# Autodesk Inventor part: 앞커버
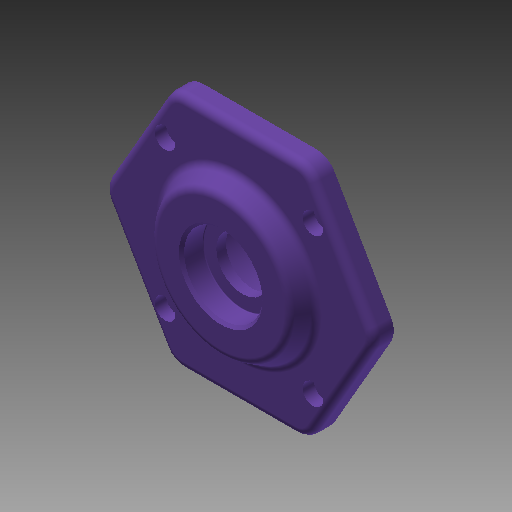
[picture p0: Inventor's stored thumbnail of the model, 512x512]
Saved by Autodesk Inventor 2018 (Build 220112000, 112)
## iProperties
Created: 2013-02
Part Number: 앞커버
Document SubType Name: Modeling
Density: 1 g/cm^3
Material: 일반
Appearance: 보라색
Author: 한국산업디자인학원[gmhk.co.kr]
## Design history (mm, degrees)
sketch "스케치1" dims "d37" = 105
  geometry: L1 (28.559, 41.466)-(50.191, 4); L2 (50.191, -4)-(28.559, -41.466); L3 (21.631, -45.466)-(-21.631, -45.466); L4 (-28.559, -41.466)-(-50.191, -4); L5 (-50.191, 4)-(-28.559, 41.466); L6 (-21.631, 45.466)-(21.631, 45.466); C1 r 30 at (0, 0); A1 r 8 centre (-43.262, 0) between (-50.191, 4) and (-50.191, -4); A2 r 8 centre (-21.631, 37.466) between (-21.631, 45.466) and (-28.559, 41.466); A3 r 8 centre (21.631, 37.466) between (28.559, 41.466) and (21.631, 45.466); A4 r 8 centre (43.262, 0) between (50.191, -4) and (50.191, 4); A5 r 8 centre (21.631, -37.466) between (21.631, -45.466) and (28.559, -41.466); A6 r 8 centre (-21.631, -37.466) between (-28.559, -41.466) and (-21.631, -45.466); 9 further points
  constraints: 12 end point, 12 point on circle, 12 point on line, 12 tangent, 7 centre point, 5 equal radius, 3 coincident, 1 horizontal, 16 other
  dimensions: "d40" = 8 radius of A1; "d41" = 60 diameter of C1
extrude "돌출1" new body sketch "스케치1" distance "d0" = 8; taper "d1" = 0 deg
sketch "스케치2"
  geometry: C1 r 30 at (0, 0); 1 further point
  constraints: 1 centre point, 1 coincident
  dimensions: "d2" = 60 diameter of C1
extrude "돌출2" join sketch "스케치2" distance "d3" = 7; taper "d4" = -30 deg
hole "구멍1" diameter "d7" = 20; stored, may be unused: countersink angle "d11" = 90 deg, drill point angle "d13" = 118 deg; dims "d8" = 6, "d9" = 30, "d10" = 8.3, "d12" = 20, "d52" = 10, "d53" = 10
sketch "스케치3"
  geometry: L1 (-28.284, 28.284)-(0, 0); L2 (0, 0)-(0, 40); L3 (0, 0)-(28.284, 28.284); L4 (0, 0)-(28.284, -28.284); L5 (0, 0)-(-28.284, -28.284); C1 r 1.621 at (28.284, 28.284); C2 r 1.621 at (-28.284, 28.284); C3 r 1.621 at (-28.284, -28.284); C4 r 1.621 at (28.284, -28.284); C5 r 10 at (0, 0) reference; A1 r 40 centre (0, 0) between (28.284, 28.284) and (-28.284, 28.284)
  constraints: 10 end point, 5 centre point, 3 perpendicular, 3 point on circle, 1 coincident, 1 vertical
  dimensions: "d48" = 80 diameter of A1; "d50" = 45 deg angle of L2 L1
hole "구멍2" sketch "스케치3" at (28.284, 28.284), (28.284, -28.284), (-28.284, -28.284), (-28.284, 28.284) diameter "d14" = 4.5; stored, may be unused: countersink angle "d18" = 90 deg, drill point angle "d20" = 118 deg; dims "d15" = 6, "d16" = 8, "d17" = 4.4, "d19" = 20
extrude "돌출3" join sketch "스케치1" distance "d21" = 12; taper "d22" = 0 deg
hole "구멍3" diameter "d25" = 30; stored, may be unused: countersink angle "d29" = 90 deg, drill point angle "d31" = 0 deg; dims "d26" = 6, "d27" = 40, "d28" = 12, "d30" = 15, "d42" = 10, "d43" = 10
fillet "모깎기1" dims "d32" = 3, "d33" = 0.3
chamfer "모따기1" distance "d34" = 1; stored, may be unused: second distance "d35" = 2, angle "d36" = 45 deg
chamfer "모따기2" distance "d44" = 1; stored, may be unused: second distance "d45" = 2, angle "d46" = 45 deg
fillet "모깎기2" dims "d47" = 3
fillet "모깎기3" dims "d54" = 0.6
node "솔리드1"
